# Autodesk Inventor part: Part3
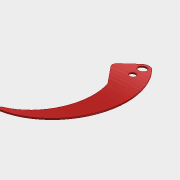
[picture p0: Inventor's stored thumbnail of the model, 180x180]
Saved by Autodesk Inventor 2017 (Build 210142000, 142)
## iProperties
Created: 2016-09
Part Number: Part3
Material: Generic
Document SubType Name: Modeling
Designer: thh71104
Density: 1 g/cm^3
Appearance: Red
Author: thh71104
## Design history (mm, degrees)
node "300730-001.dwg"
sketch "Sketch1"
  geometry: L1 (-88.821, -35.221)-(-22.551, 24.87) reference; L2 (-24.034, -159.9)-(-92.05, -67.197) reference; L3 (233.842, 33.572)-(239.842, 33.572) reference; L4 (239.842, 33.572)-(239.842, -481.085) reference; L5 (233.842, -481.085)-(233.842, 33.572) reference; C1 r 20 at (0, 0) reference; C2 r 15 at (0, -57) reference; A1 r 336 centre (-256.7, -159.9) between (-157.133, -480.809) and (28.495, 17.75) reference; A2 r 33.572 centre (0, 0) between (28.495, 17.75) and (-22.551, 24.87) reference; A3 r 24 centre (-72.7, -53) between (-88.821, -35.221) and (-92.05, -67.197) reference; A4 r 263 centre (-276.7, -232.9) between (-161.648, -469.399) and (-24.034, -159.9) reference; A5 r 6.153 centre (-158.956, -474.932) between (-161.648, -469.399) and (-157.133, -480.809) reference; 1 further point
  dimensions: "d1" = 6 distance between parallel lines of L4 L5 (derived)
extrude "Extrusion1" new body sketch "Sketch1" stored distance "d2" = 6 (= d1); taper "d3" = 0 deg
body "Solid1"
other parameters: "d0" = 0
